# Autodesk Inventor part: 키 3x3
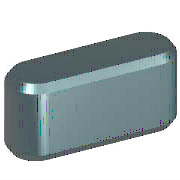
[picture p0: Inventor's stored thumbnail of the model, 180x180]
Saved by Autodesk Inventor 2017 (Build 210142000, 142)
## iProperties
Created: 2012-02
Part Number: 키 3x3
Material: 강철, 연강
Description: 키 및 해당 키홈
Document SubType Name: Modeling
Standard: KS B 1311
Designer: mduedu
Standards Organization: KS
Language: ko-KR
Size Designation: 3 x 3 x 12
Categories: <MemberInstance><Categories><Category DisplayName="샤프트 부품" InternalName="7f7aeb1f-a693-4053-b835-cee3144e0d98" Mnemonic="SHFT"><Category DisplayName="키" Interna
Density: 1 g/cm^3
Appearance: 노란색
IsCustomPart: 1
Author: mduedu
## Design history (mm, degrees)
workplane "Work Plane1"
workplane "Work Plane2"
sketch "스케치1"
  geometry: L1 (1.5, 1.5)-(10.5, 1.5); L2 (10.5, -1.5)-(1.5, -1.5); L3 (0, 9.4)-(0, -7.4) reference; L4 (-5, 0)-(30, 0) reference; L5 (12, 0)-(12, 7); A1 r 1.5 centre (1.5, 0) between (1.5, 1.5) and (1.5, -1.5); A2 r 1.5 centre (10.5, 0) between (10.5, -1.5) and (10.5, 1.5)
  constraints: 6 end point, 5 point on circle, 4 tangent, 3 point on line, 2 centre point, 1 horizontal, 1 parallel, 1 perpendicular
  dimensions: "d0" = 1.5 radius of A1 (= 0.5 x PB); "d13" = 1.5 radius of A2 (= 0.5 x PB); "d14" = 12 distance between parallel lines of L5 L3 (= NLG)
extrude "본체1" new body sketch "스케치1" taper "d3" = 0 deg; stored distance "d4" = 10
workplane "Work Plane3"
body "Solid1"
chamfer "모따기1" distance "d8" = 0.25 (= PHH); stored, may be unused: second distance "d9" = 0.25 (= PHH), angle "d15" = 45 deg
other parameters: "d1" = -1.8 (= -PNT), "d2" = 1.2 (= PH - PNT), "NLG" = 12 [user parameter; used in 3 equation terms], "PB" = 3 [user parameter; used in 2 equation terms], "PNT" = 1.8 [user parameter; used in 2 equation terms], "PH" = 3 [user parameter; used in 1 equation term], "PHH" = 0.25 [user parameter; used in 2 equation terms], "d10" = 0, "d16" = 0, "d17" = 0, "d18" = 0, "WDMIN" = 8 [user parameter], "PLB2" = 12 (= NLG) [user parameter], "PLB1" = 12 (= NLG) [user parameter], "RR" = 0.08 [user parameter], "PUEB" = 1.4 [user parameter]
